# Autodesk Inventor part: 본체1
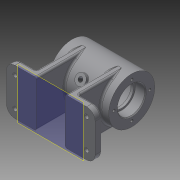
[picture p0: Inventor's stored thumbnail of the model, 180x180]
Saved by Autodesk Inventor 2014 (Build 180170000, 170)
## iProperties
Created: 2017-02
Part Number: 본체1
Material: 일반
Document SubType Name: Modeling
Designer: owner
Density: 1 g/cm^3
Appearance: 기본값
Author: owner
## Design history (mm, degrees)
sketch "스케치1"
  geometry: L1 (0, 0)-(70, 0); L2 (0, 16)-(0, 27); L3 (0, 27)-(70, 27); L4 (70, 27)-(70, 16); L5 (0, 16)-(12, 16); L6 (12, 16)-(12, 14); L7 (12, 14)-(15, 14); L8 (15, 14)-(15, 22); L9 (15, 22)-(55, 22); L10 (55, 22)-(55, 14); L11 (55, 14)-(58, 14); L12 (58, 14)-(58, 16); L13 (58, 16)-(70, 16)
  constraints: 26 end point, 6 parallel, 6 perpendicular, 2 collinear, 2 horizontal alignment, 2 vertical alignment, 1 horizontal
  dimensions: "d0" = 70 distance of L1.start L1.end; "d1" = 54 diameter of L3 L1; "d2" = 32 diameter of L5 L1; "d3" = 28 diameter of L7 L1; "d4" = 44 diameter of L9 L1; "d5" = 12 distance of L4.end L12.end; "d6" = 40 distance of L8.end L9.end
revolve "회전1" sketch "스케치1" stored, may be unused: angle "d7" = 90 deg
node "작업 평면1"
sketch "스케치2"
  geometry: L1 (17, -27)-(17, 27); L2 (-87, 27)-(-87, -27); L3 (-70, 0)-(8.164, 0); L4 (0, 27)-(0, -27) reference; L5 (-52, 27)-(-52, -27); L6 (-18, 27)-(-18, -27); L7 (17, 27)-(-18, 27); L8 (-52, 27)-(-87, 27); L9 (-87, -27)-(-52, -27); L10 (-18, -27)-(17, -27); L11 (-35, 27)-(-35, -27)
  constraints: 20 end point, 8 perpendicular, 4 parallel
  dimensions: "d19" = 52 distance between parallel lines of L2 L11; "d20" = 52 distance between parallel lines of L1 L11; "d21" = 17 distance between parallel lines of L5 L11; "d22" = 17 distance between parallel lines of L6 L11; "d23" = 54 distance of L2.start L2.end
extrude "돌출1" join sketch "스케치2" distance "d24" = 8; taper "d25" = 0 deg
sketch "스케치4"
  geometry: L1 (-17, -27)-(18, -27) reference; L2 (18, -27)-(18, 27) reference; L3 (18, 27)-(-17, 27) reference; L4 (52, 27)-(87, 27) reference; L5 (52, -27)-(52, 27) reference; L6 (87, -27)-(52, -27) reference; L7 (10, -27)-(10, 27); L8 (60, -27)-(60, 27); 1 further point
  constraints: 4 end point, 4 point on line, 2 perpendicular
  dimensions: "d28" = 8 distance between parallel lines of L2 L7; "d29" = 8 distance between parallel lines of L8 L5
extrude "돌출2" join sketch "스케치4" stored distance "d30" = 8; taper "d31" = 0 deg
node "작업 평면2"
sketch "스케치5"
  geometry: L1 (0, 27)-(-70, 27) reference; L2 (-70, 27)-(-70, -27) reference; C1 r 5 at (-45, 0); 1 further point
  constraints: 1 centre point, 1 horizontal alignment
  dimensions: "d33" = 10 diameter of C1; "d52" = 25 distance from line of C1.centre L2
extrude "돌출3" join sketch "스케치5" stored distance "d34" = 8; taper "d35" = 0 deg
hole "구멍1" diameter "d38" = 5.188; stored, may be unused: countersink angle "d42" = 90 deg, drill point angle "d44" = 118 deg; dims "d39" = 6, "d40" = 4, "d41" = 2, "d43" = 10, "d132" = 10, "d133" = 10
node "작업 평면6"
  node "작업 평면5"
sketch "스케치7"
  geometry: L1 (0, 27)-(70, 27) reference; L2 (0, -27)-(0, 27) reference; C1 r 6 at (35, 0); 1 further point
  constraints: 1 centre point, 1 horizontal alignment
  dimensions: "d53" = 12 diameter of C1; "d98" = 35 distance from line of C1.centre L2
extrude "돌출5" join sketch "스케치7" stored distance "d54" = 8; taper "d55" = 0 deg
hole "구멍2" diameter "d58" = 5.188; stored, may be unused: countersink angle "d62" = 90 deg, drill point angle "d64" = 118 deg; dims "d59" = 6, "d60" = 4, "d61" = 2, "d63" = 8, "d65" = 10, "d66" = 10
fillet "모깎기1" dims "d67" = 10
sketch "스케치8" dims "d68" = 9
  geometry: L1 (74.402, 12.5)-(71.804, 17); L2 (71.804, 17)-(74.402, 21.5); L3 (74.402, 21.5)-(79.598, 21.5); L4 (79.598, 21.5)-(82.196, 17); L5 (82.196, 17)-(79.598, 12.5); L6 (79.598, 12.5)-(74.402, 12.5); C1 r 2.5 at (77, 17); A1 r 10 centre (77, 17) between (87, 17) and (77, 27) reference; 7 further points
  constraints: 12 end point, 6 coincident, 1 centre point, 1 midpoint, 1 vertical alignment, 15 other
  dimensions: "d69" = 5 diameter of C1; "d148" = 4.5 vertical distance of L4.end L5.end
sketch "스케치9" dims "d74" = 9, "d75" = 9, "d76" = 9
  geometry: L1 (-4.113, 21.32)-(-1.815, 16.66); L2 (-1.815, 16.66)-(-4.702, 12.34); L3 (-4.702, 12.34)-(-9.887, 12.68); L4 (-9.887, 12.68)-(-12.185, 17.34); L5 (-12.185, 17.34)-(-9.298, 21.66); L6 (-9.298, 21.66)-(-4.113, 21.32); L7 (-4.113, -12.68)-(-1.815, -17.34); L8 (-1.815, -17.34)-(-4.702, -21.66); L9 (-4.702, -21.66)-(-9.887, -21.32); L10 (-9.887, -21.32)-(-12.185, -16.66); L11 (-12.185, -16.66)-(-9.298, -12.34); L12 (-9.298, -12.34)-(-4.113, -12.68); L13 (79.887, -12.68)-(82.185, -17.34); L14 (82.185, -17.34)-(79.298, -21.66); L15 (79.298, -21.66)-(74.113, -21.32); L16 (74.113, -21.32)-(71.815, -16.66); L17 (71.815, -16.66)-(74.702, -12.34); L18 (74.702, -12.34)-(79.887, -12.68); C1 r 2.5 at (-7, 17); C2 r 2.5 at (-7, -17); C3 r 2.5 at (77, -17); A1 r 10 centre (-7, -17) between (-17, -17) and (-7, -27) reference; A2 r 10 centre (-7, 17) between (-7, 27) and (-17, 17) reference; A3 r 10 centre (77, -17) between (77, -27) and (87, -17) reference; 16 further points
  constraints: 36 end point, 15 coincident, 3 centre point, 3 midpoint, 48 other
  dimensions: "d77" = 5 diameter of C1; "d78" = 5 diameter of C2; "d79" = 5 diameter of C3; "d134" = 2.88675 horizontal distance of L17.end L16.end; "d135" = 2.88675 horizontal distance of L10.end L11.end; "d136" = 2.88675 horizontal distance of L4.end L5.end
fillet "모깎기2" dims "d88" = 3
fillet "모깎기3" dims "d89" = 3
chamfer "모따기1" distance "d90" = 1; stored, may be unused: second distance "d91" = 2, angle "d92" = 45 deg
fillet "모깎기4" dims "d93" = 0.3
fillet "모깎기5" dims "d94" = 0.3
sketch "스케치10"
  geometry: C1 r 27 at (0, 0) reference; 1 further point
  constraints: 1 vertical alignment
  dimensions: "d99" = 21 distance of C1.centre point (0, 21)
hole "구멍3" sketch "스케치10" at (0, 21) diameter "d100" = 3.242; stored, may be unused: countersink angle "d104" = 90 deg, drill point angle "d106" = 118 deg; dims "d101" = 8, "d102" = 4, "d103" = 2, "d105" = 10
sketch "스케치11"
  geometry: C1 r 27 at (0, 0) reference; 1 further point
  constraints: 1 vertical alignment
  dimensions: "d110" = 21 distance of C1.centre point (0, 21)
hole "구멍4" sketch "스케치11" at (0, 21) diameter "d111" = 3.242; stored, may be unused: countersink angle "d115" = 90 deg, drill point angle "d117" = 118 deg; dims "d112" = 8, "d113" = 4, "d114" = 2, "d116" = 10
fillet "모깎기15" dims "d130" = 2
fillet "모깎기16" dims "d131" = 2
extrude "돌출12" cut sketch "스케치9" distance "d137" = 4; taper "d138" = 0 deg
extrude "돌출17" cut sketch "스케치9" stored distance "d149" = 3; taper "d150" = 0 deg
extrude "돌출19" cut sketch "스케치8" stored distance "d153" = 3; taper "d154" = 0 deg
extrude "돌출20" cut sketch "스케치9" distance "d155" = 3; taper "d156" = 0 deg
extrude "돌출21" cut sketch "스케치9" distance "d157" = 3; taper "d158" = 0 deg
extrude "돌출22" cut sketch "스케치9" distance "d159" = 3; taper "d160" = 0 deg
extrude "돌출23" cut sketch "스케치8" distance "d161" = 3; taper "d162" = 0 deg
node "솔리드1"
pattern_circular "원형 패턴1" dims angle "d108" = 360 deg
pattern_circular "원형 패턴2" dims angle "d119" = 360 deg
node "작업축1"
other parameters: "d32" = 92, "d47" = 57 deg
